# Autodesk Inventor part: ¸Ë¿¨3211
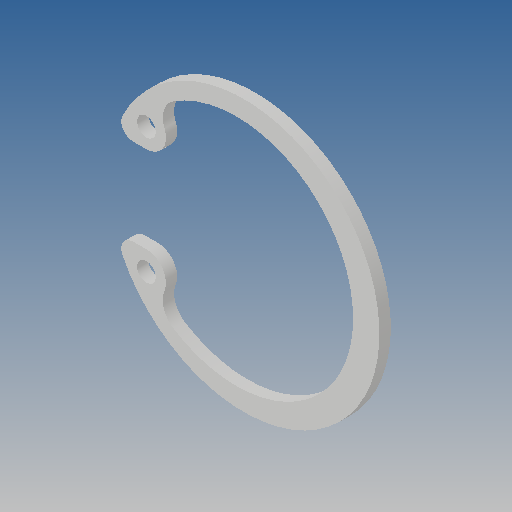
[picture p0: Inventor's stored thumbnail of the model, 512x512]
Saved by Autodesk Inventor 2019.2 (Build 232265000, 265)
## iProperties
Created: 2013-07
Part Number: ¸Ë¿¨3211
Material: Ogólny
Document SubType Name: Modeling
Designer: CADENGINEERING4
Density: 1 g/cm^3
Appearance: Domyślna
Author: CADENGINEERING4
Revision Number: ÈÎºÎ
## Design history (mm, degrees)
feature "Í¹Ì¨-À­Éì1"
node "Bryła1"
